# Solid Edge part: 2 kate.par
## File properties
Author: Henri
Template: Normal.par
Last saved by: Henri
Revision: 46
Application: Solid Edge
Accuracy: 0,990
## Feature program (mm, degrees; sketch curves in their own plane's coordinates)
sketch for "unnamed Protrusion 1" plane through (0, 0, 0) normal (0, 0, 1) x-axis (1, 0, 0)
  line (202.5, -60) -> (212.5, -60)
  line (212.5, -60) -> (212.5, -55)
  line (212.5, -55) -> (202.5, -55)
  line (202.5, -55) -> (202.5, -60)
extrude "unnamed Protrusion 1" add finite 10 along -normal
sketch for "ExtrudedProtrusion_2" plane through (0, 0, 0) normal (0, 0, 1) x-axis (1, 0, 0)
  line (261, -467.8017) -> (261, -32.1983)
  line (-262.5, 65.8312) -> (-262.5, -565.8312)
extrude "ExtrudedProtrusion_2" add finite 5 along -normal
fillet "Round_1" radius 1.5
lofted protrusion "unnamed LoftedProtrusion 1"
fillet "Round_15" radius 5
sketch for "ExtrudedCutout_2" plane through (-55, -250, 90) normal (0, 0, 1) x-axis (0, 1, 0)
  line (-225, 137.5) -> (225, 137.5)
  line (225, 137.5) -> (225, -137.5)
  line (-225, -137.5) -> (225, -137.5)
  line (-225, 137.5) -> (-225, -137.5)
extrude "ExtrudedCutout_2" cut finite 5 along -normal
thinwall "Thinwall_6"  Thickness = 5 mm
sketch used by "ExtrudedProtrusion_3" plane through (0, 0, 0) normal (0, 0, 1) x-axis (1, 0, 0)
  line (-207.5, -75) -> (-207.5, -425)
  line (-207.5, -425) -> (242.5, -425)
  line (242.5, -75) -> (242.5, -425)
  line (-207.5, -75) -> (242.5, -75)
  line (-210, -72.5) -> (245, -72.5)
  line (245, -72.5) -> (245, -427.5)
  line (245, -427.5) -> (-210, -427.5)
  line (-210, -72.5) -> (-210, -427.5)
  dimension (linear) = 207.5
  dimension (linear) = 207.5
extrude "ExtrudedProtrusion_3" add finite 42.5 along -normal
sketch for "ExtrudedCutout_4" plane through (0, 0, 0) normal (0, 0, 1) x-axis (1, 0, 0)
extrude "ExtrudedCutout_4" cut finite 40 along -normal
sketch for "ExtrudedCutout_5" plane through (18.5864, -250.0758, 0) normal (0, 0, 1) x-axis (0, 1, 0)
  line (240.0758, -138.9136) -> (175.0758, -138.9136)
  line (175.0758, -78.9136) -> (175.0758, -138.9136)
  line (240.0758, -78.9136) -> (175.0758, -78.9136)
  arc centre (240.0758, -88.9136) radius 10 from (240.0758, -78.9136) to (250.0758, -88.9136) cw
  line (250.0758, -88.9136) -> (250.0758, -128.9136)
  arc centre (240.0758, -128.9136) radius 10 from (250.0758, -128.9136) to (240.0758, -138.9136) cw
extrude "ExtrudedCutout_5" cut finite 40 along -normal
lofted protrusion "unnamed LoftedProtrusion 2"
lofted cutout "unnamed LoftedCutout 1"
fillet "Round_17" radius 1.5
mirror "unnamed Mirror 1" of "ExtrudedCutout_5", "unnamed LoftedProtrusion 2", "unnamed LoftedCutout 1", "Round_17" about plane through (0, -250, 0) normal (0, -1, 0)
extrude "unnamed Cutout 1" cut finite 40
lofted protrusion "unnamed LoftedProtrusion 3"
lofted cutout "unnamed LoftedCutout 2"
fillet "unnamed Round 1"
sketch for "unnamed Cutout 2" #1 plane through (178.0953, -250, 44.6428) normal (0.514496, 0, 0.857493) x-axis (0, 1, 0)
  line (-205, 61.7735) -> (-15, 61.7735)
  arc centre (-15, 51.7735) radius 10 from (-15, 61.7735) to (-5, 51.7735) cw
  line (-5, 51.7735) -> (-5, -51.7701)
  arc centre (-15, -51.7701) radius 10 from (-15, -61.7701) to (-5, -51.7701) ccw
  line (-15, -61.7701) -> (-205, -61.7701)
  arc centre (-205, -51.7701) radius 10 from (-215, -51.7701) to (-205, -61.7701) ccw
  line (-215, -51.7701) -> (-215, 51.7735)
  arc centre (-205, 51.7735) radius 10 from (-215, 51.7735) to (-205, 61.7735) cw
sketch for "unnamed Cutout 2" #2 plane through (178.0953, -250, 44.6428) normal (0.514496, 0, 0.857493) x-axis (0, 1, 0)
  line (15, 61.7735) -> (205.778, 61.7735)
  arc centre (205.778, 52.5515) radius 9.222 from (215, 52.5515) to (205.778, 61.7735) ccw
  line (215, 52.5515) -> (215, -52.5481)
  arc centre (205.778, -52.5481) radius 9.222 from (205.778, -61.7701) to (215, -52.5481) ccw
  line (205.778, -61.7701) -> (15, -61.7701)
  arc centre (15, -51.7701) radius 10 from (5, -51.7701) to (15, -61.7701) ccw
  line (5, -51.7701) -> (5, 51.7735)
  arc centre (15, 51.7735) radius 10 from (5, 51.7735) to (15, 61.7735) cw
extrude "unnamed Cutout 2" cut through along -normal
sketch for "ExtrudedProtrusion_9" #1 plane through (17.5, -250, -40) normal (0, 0, 1) x-axis (0, 1, 0)
  line (-94.7295, 225) -> (-89.7295, 225)
  line (-89.7295, 97.5) -> (-89.7295, 225)
  line (-175, 97.5) -> (-89.7295, 97.5)
  line (-175, 102.5) -> (-175, 97.5)
  line (-175, 102.5) -> (-94.7295, 102.5)
  line (-94.7295, 102.5) -> (-94.7295, 225)
sketch for "ExtrudedProtrusion_9" #2 plane through (17.5, -250, -40) normal (0, 0, 1) x-axis (0, 1, 0)
  line (89.7295, -30) -> (89.7295, 225)
  line (89.7295, 225) -> (94.7295, 225)
  line (94.7295, -25) -> (94.7295, 225)
  line (94.7295, -25) -> (175, -25)
  line (175, -25) -> (175, -30)
  line (175, -30) -> (89.7295, -30)
extrude "ExtrudedProtrusion_9" add finite 40 along +normal
sketch for "unnamed Protrusion 2" plane through (-55, -475, 87.5) normal (0, 1, 0) x-axis (-1, 0, 0)
  line (25, -87.5) -> (25, -2.5)
  line (30, -2.5) -> (25, -2.5)
  line (30, -2.5) -> (30, -87.5)
  line (30, -87.5) -> (25, -87.5)
extrude "unnamed Protrusion 2" add through along -normal
sketch for "unnamed Protrusion 3" plane through (-55, -25, 87.5) normal (0, -1, 0) x-axis (1, 0, 0)
  line (102.5, -2.5) -> (102.5, -87.5)
  line (97.5, -87.5) -> (102.5, -87.5)
  line (97.5, -2.5) -> (97.5, -87.5)
  line (97.5, -2.5) -> (102.5, -2.5)
extrude "unnamed Protrusion 3" add through along -normal
sketch for "ExtrudedProtrusion_12" #1 plane through (18.5864, -250.0758, 0) normal (0, 0, 1) x-axis (0, 1, 0)
  line (89.8053, -28.9136) -> (89.8053, 226.0864)
  line (89.8053, 226.0864) -> (94.8053, 226.0864)
  line (94.8053, -23.9136) -> (94.8053, 226.0864)
  line (94.8053, -23.9136) -> (225.0758, -23.9136)
  line (225.0758, -23.9136) -> (225.0758, -28.9136)
  line (225.0758, -28.9136) -> (89.8053, -28.9136)
sketch for "ExtrudedProtrusion_12" #2 plane through (18.5864, -250.0758, 0) normal (0, 0, 1) x-axis (0, 1, 0)
  line (-224.9242, 98.5864) -> (-89.6537, 98.5864)
  line (-89.6537, 98.5864) -> (-89.6537, 226.0864)
  line (-94.6537, 226.0864) -> (-89.6537, 226.0864)
  line (-94.6537, 103.5864) -> (-94.6537, 226.0864)
  line (-224.9242, 103.5864) -> (-94.6537, 103.5864)
  line (-224.9242, 103.5864) -> (-224.9242, 98.5864)
extrude "ExtrudedProtrusion_12" add finite 85 along +normal
sketch for "unnamed Cutout 3" #1 plane through (0.1912, -510.5703, 43.2891) normal (0, -0.948683, 0.316228) x-axis (1, 0, 0)
  line (-72.6912, 10.6338) -> (17.3088, 10.6338)
  arc centre (17.3088, 15.6338) radius 5 from (17.3088, 10.6338) to (22.3088, 15.6338) ccw
  line (22.3088, 30.6338) -> (22.3088, 15.6338)
  arc centre (17.3088, 30.6338) radius 5 from (22.3088, 30.6338) to (17.3088, 35.6338) ccw
  line (-72.6912, 35.6338) -> (17.3088, 35.6338)
  arc centre (-72.6912, 30.6338) radius 5 from (-77.6912, 30.6338) to (-72.6912, 35.6338) cw
  line (-77.6912, 30.6338) -> (-77.6912, 15.6338)
  arc centre (-72.6912, 15.6338) radius 5 from (-77.6912, 15.6338) to (-72.6912, 10.6338) ccw
sketch for "unnamed Cutout 3" #2 plane through (0.1912, -510.5703, 43.2891) normal (0, -0.948683, 0.316228) x-axis (1, 0, 0)
  line (-182.6912, 10.6338) -> (-92.6912, 10.6338)
  arc centre (-92.6912, 15.6338) radius 5 from (-92.6912, 10.6338) to (-87.6912, 15.6338) ccw
  line (-87.6912, 30.6338) -> (-87.6912, 15.6338)
  arc centre (-92.6912, 30.6338) radius 5 from (-87.6912, 30.6338) to (-92.6912, 35.6338) ccw
  line (-182.6912, 35.6338) -> (-92.6912, 35.6338)
  arc centre (-182.6912, 30.6338) radius 5 from (-187.6912, 30.6338) to (-182.6912, 35.6338) cw
  line (-187.6912, 30.6338) -> (-187.6912, 15.6338)
  arc centre (-182.6912, 15.6338) radius 5 from (-187.6912, 15.6338) to (-182.6912, 10.6338) ccw
extrude "unnamed Cutout 3" cut through along -normal
sketch for "unnamed Cutout 4" #1 plane through (0.1912, 10.5703, 43.2891) normal (0, 0.948683, 0.316228) x-axis (-1, 0, 0)
  line (0, 0) -> (0, 0)
  arc centre (92.6912, 30.6338) radius 5 from (87.6912, 30.6338) to (92.6912, 35.6338) cw
  line (92.6912, 35.6338) -> (182.6912, 35.6338)
  arc centre (182.6912, 30.6338) radius 5 from (187.6912, 30.6338) to (182.6912, 35.6338) ccw
  line (187.6912, 30.6338) -> (187.6912, 15.6338)
  arc centre (182.6912, 15.6338) radius 5 from (182.6912, 10.6338) to (187.6912, 15.6338) ccw
  line (92.6912, 10.6338) -> (182.6912, 10.6338)
  arc centre (92.6912, 15.6338) radius 5 from (87.6912, 15.6338) to (92.6912, 10.6338) ccw
  line (87.6912, 30.6338) -> (87.6912, 15.6338)
sketch for "unnamed Cutout 4" #2 plane through (0.1912, 10.5703, 43.2891) normal (0, 0.948683, 0.316228) x-axis (-1, 0, 0)
  line (-17.3088, 35.6338) -> (72.6912, 35.6338)
  arc centre (72.6912, 30.6338) radius 5 from (77.6912, 30.6338) to (72.6912, 35.6338) ccw
  line (77.6912, 30.6338) -> (77.6912, 15.6338)
  arc centre (72.6912, 15.6338) radius 5 from (72.6912, 10.6338) to (77.6912, 15.6338) ccw
  line (-17.3088, 10.6338) -> (72.6912, 10.6338)
  arc centre (-17.3088, 15.6338) radius 5 from (-22.3088, 15.6338) to (-17.3088, 10.6338) ccw
  line (-22.3088, 30.6338) -> (-22.3088, 15.6338)
  arc centre (-17.3088, 30.6338) radius 5 from (-22.3088, 30.6338) to (-17.3088, 35.6338) cw
extrude "unnamed Cutout 4" cut through along -normal
sketch for "unnamed Cutout 5" #1 plane through (-212.5, -250, 42.4987) normal (-1, 0, 0) x-axis (0, -1, 0)
  line (224.7295, 17.5013) -> (109.7295, 17.5013)
  arc centre (109.7295, 22.5013) radius 5 from (104.7295, 22.5013) to (109.7295, 17.5013) ccw
  line (104.7295, 27.5013) -> (104.7295, 22.5013)
  arc centre (109.7295, 27.5013) radius 5 from (104.7295, 27.5013) to (109.7295, 32.5013) cw
  line (109.7295, 32.5013) -> (224.7295, 32.5013)
  arc centre (224.7295, 27.5013) radius 5 from (224.7295, 32.5013) to (229.7295, 27.5013) cw
  line (229.7295, 27.5013) -> (229.7295, 22.5013)
  arc centre (224.7295, 22.5013) radius 5 from (229.7295, 22.5013) to (224.7295, 17.5013) cw
sketch for "unnamed Cutout 5" #2 plane through (-212.5, -250, 42.4987) normal (-1, 0, 0) x-axis (0, -1, 0)
  line (-109.7295, 17.5013) -> (-224.7295, 17.5013)
  arc centre (-224.7295, 22.5013) radius 5 from (-229.7295, 22.5013) to (-224.7295, 17.5013) ccw
  line (-229.7295, 27.5013) -> (-229.7295, 22.5013)
  arc centre (-224.7295, 27.5013) radius 5 from (-229.7295, 27.5013) to (-224.7295, 32.5013) cw
  line (-224.7295, 32.5013) -> (-109.7295, 32.5013)
  arc centre (-109.7295, 27.5013) radius 5 from (-109.7295, 32.5013) to (-104.7295, 27.5013) cw
  line (-104.7295, 27.5013) -> (-104.7295, 22.5013)
  arc centre (-109.7295, 22.5013) radius 5 from (-109.7295, 17.5013) to (-104.7295, 22.5013) ccw
extrude "unnamed Cutout 5" cut through along -normal
sketch for "unnamed Protrusion 4" plane through (146.5099, -250.0758, 0) normal (0, 0, 1) x-axis (0, 1, 0)
  arc centre (-4.4242, 34.0099) radius 10 from (-4.4242, 24.0099) to (-14.4242, 34.0099) cw
  line (-14.4242, 53.0099) -> (-14.4242, 34.0099)
  arc centre (-4.4242, 53.0099) radius 10 from (-14.4242, 53.0099) to (-4.4242, 63.0099) cw
  line (-4.4242, 63.0099) -> (4.5758, 63.0099)
  arc centre (4.5758, 53.0099) radius 10 from (4.5758, 63.0099) to (14.5758, 53.0099) cw
  line (14.5758, 53.0099) -> (14.5758, 34.0099)
  arc centre (4.5758, 34.0099) radius 10 from (14.5758, 34.0099) to (4.5758, 24.0099) cw
  line (-4.4242, 24.0099) -> (4.5758, 24.0099)
extrude "unnamed Protrusion 4" add through along +normal
sketch for "unnamed Cutout 6" plane through (146.5099, -250.0758, 0) normal (0, 0, 1) x-axis (0, 1, 0)
  arc centre (-4.4242, 34.0099) radius 3 from (-4.4242, 31.0099) to (-7.4242, 34.0099) cw
  line (-7.4242, 53.0099) -> (-7.4242, 34.0099)
  arc centre (-4.4242, 53.0099) radius 3 from (-7.4242, 53.0099) to (-4.4242, 56.0099) cw
  line (-4.4242, 56.0099) -> (4.5758, 56.0099)
  arc centre (4.5758, 53.0099) radius 3 from (4.5758, 56.0099) to (7.5758, 53.0099) cw
  line (7.5758, 53.0099) -> (7.5758, 34.0099)
  arc centre (4.5758, 34.0099) radius 3 from (7.5758, 34.0099) to (4.5758, 31.0099) cw
  line (-4.4242, 31.0099) -> (4.5758, 31.0099)
extrude "unnamed Cutout 6" cut through along +normal
sketch for "unnamed Cutout 7" plane through (146.5099, -250.0758, 0) normal (0, 0, 1) x-axis (0, 1, 0)
extrude "unnamed Cutout 7" cut through along -normal
fillet "Round_20" radius 5
sketch for "ExtrudedCutout_17" plane through (-212.5, -250, 42.4987) normal (-1, 0, 0) x-axis (0, -1, 0)
extrude "ExtrudedCutout_17" cut finite 10 symmetric
sketch for "unnamed Cutout 8" plane through (47.5, -70.2705, 22.5) normal (1, 0, 0) x-axis (0, 1, 0)
  line (-19.7295, 37) -> (-19.7295, -60)
  line (-19.7295, -60) -> (-69.7295, -60)
  line (-69.7295, -60) -> (-69.7295, 37)
  arc centre (-66.7295, 37) radius 3 from (-69.7295, 37) to (-66.7295, 40) cw
  line (-66.7295, 40) -> (-22.7295, 40)
  arc centre (-22.7295, 37) radius 3 from (-22.7295, 40) to (-19.7295, 37) cw
extrude "unnamed Cutout 8" cut through along -normal
sketch for "ExtrudedProtrusion_19" #1 plane through (74.4134, -250.0013, 0) normal (0, 0, 1) x-axis (0, 1, 0)
sketch for "ExtrudedProtrusion_19" #2 plane through (74.4134, -250.0013, 0) normal (0, 0, 1) x-axis (0, 1, 0)
sketch for "ExtrudedProtrusion_19" #3 plane through (74.4134, -250.0013, 0) normal (0, 0, 1) x-axis (0, 1, 0)
  circle centre (312.0066, 264.4134) radius 1.25
sketch for "ExtrudedProtrusion_19" #4 plane through (74.4134, -250.0013, 0) normal (0, 0, 1) x-axis (0, 1, 0)
  circle centre (313.1686, 134.4134) radius 1.25
sketch for "ExtrudedProtrusion_19" #5 plane through (74.4134, -250.0013, 0) normal (0, 0, 1) x-axis (0, 1, 0)
sketch for "ExtrudedProtrusion_19" #6 plane through (74.4134, -250.0013, 0) normal (0, 0, 1) x-axis (0, 1, 0)
sketch for "ExtrudedProtrusion_19" #7 plane through (74.4134, -250.0013, 0) normal (0, 0, 1) x-axis (0, 1, 0)
sketch for "ExtrudedProtrusion_19" #8 plane through (74.4134, -250.0013, 0) normal (0, 0, 1) x-axis (0, 1, 0)
sketch for "ExtrudedProtrusion_19" #9 plane through (74.4134, -250.0013, 0) normal (0, 0, 1) x-axis (0, 1, 0)
  circle centre (285.719, -125.5866) radius 1.25
sketch for "ExtrudedProtrusion_19" #10 plane through (74.4134, -250.0013, 0) normal (0, 0, 1) x-axis (0, 1, 0)
  circle centre (226.2112, -190.5866) radius 1.25
sketch for "ExtrudedProtrusion_19" #11 plane through (74.4134, -250.0013, 0) normal (0, 0, 1) x-axis (0, 1, 0)
  circle centre (250.0012, -306.6723) radius 1.25
extrude "ExtrudedProtrusion_19" add finite 46 along +normal
swept protrusion "unnamed SweptProtrusion 1"
mirror "unnamed Mirror 2" of "unnamed SweptProtrusion 1", "ExtrudedProtrusion_19" about plane through (0, -250, 0) normal (0, -1, 0)
sketch for "unnamed Protrusion 5" #1
  line (94.7295, -25) -> (94.7295, 225)
  line (94.7295, -25) -> (175, -25)
  line (175, -30) -> (89.7295, -30)
  line (89.7295, -30) -> (89.7295, 225)
  line (89.7295, 225) -> (94.7295, 225)
  line (-89.7295, 97.5) -> (-89.7295, 225)
  line (-94.7295, 225) -> (-89.7295, 225)
  line (175, -25) -> (175, -30)
  line (-175, 102.5) -> (-94.7295, 102.5)
  line (-175, 97.5) -> (-89.7295, 97.5)
  line (-175, 102.5) -> (-175, 97.5)
  line (-94.7295, 102.5) -> (-94.7295, 225)
  dimension (linear) = 175
sketch for "unnamed Protrusion 5" #7
  line (94.7295, -25) -> (94.7295, 225)
  line (94.7295, -25) -> (175, -25)
  line (175, -30) -> (89.7295, -30)
  line (89.7295, -30) -> (89.7295, 225)
  line (89.7295, 225) -> (94.7295, 225)
  line (-89.7295, 97.5) -> (-89.7295, 225)
  line (-94.7295, 225) -> (-89.7295, 225)
  line (175, -25) -> (175, -30)
  line (-175, 102.5) -> (-94.7295, 102.5)
  line (-175, 97.5) -> (-89.7295, 97.5)
  line (-175, 102.5) -> (-175, 97.5)
  line (-94.7295, 102.5) -> (-94.7295, 225)
  dimension (linear) = 175
extrude "unnamed Protrusion 5" add finite 46
swept protrusion "unnamed SweptProtrusion 2"
sketch for "ExtrudedProtrusion_21" plane through (-82.9156, -27.2196, 0) normal (0, 0, 1) x-axis (0, 1, 0)
  line (-42.7804, 114.5844) -> (37.2196, 114.5844)
  arc centre (37.2196, 109.5844) radius 5 from (37.2196, 114.5844) to (42.2196, 109.5844) cw
  line (42.2196, 109.5844) -> (42.2196, 9.5844)
  arc centre (37.2196, 9.5844) radius 5 from (42.2196, 9.5844) to (37.2196, 4.5844) cw
  line (-42.7804, 4.5844) -> (37.2196, 4.5844)
  arc centre (-42.7804, 9.5844) radius 5 from (-47.7804, 9.5844) to (-42.7804, 4.5844) ccw
  line (-47.7804, 109.5844) -> (-47.7804, 9.5844)
  arc centre (-42.7804, 109.5844) radius 5 from (-42.7804, 114.5844) to (-47.7804, 109.5844) ccw
extrude "ExtrudedProtrusion_21" add finite 2.5 along +normal
swept protrusion "unnamed SweptProtrusion 3"
sketch for "ExtrudedProtrusion_22" #1 plane through (-142.5, -30, 2.5) normal (0, 0, 1) x-axis (0, 1, 0)
  circle centre (-25, 51.5) radius 1
sketch for "ExtrudedProtrusion_22" #2 plane through (-142.5, -30, 2.5) normal (0, 0, 1) x-axis (0, 1, 0)
  circle centre (-15, 51.5) radius 1
sketch for "ExtrudedProtrusion_22" #3 plane through (-142.5, -30, 2.5) normal (0, 0, 1) x-axis (0, 1, 0)
  circle centre (-5, 51.5) radius 1
sketch for "ExtrudedProtrusion_22" #4 plane through (-142.5, -30, 2.5) normal (0, 0, 1) x-axis (0, 1, 0)
  circle centre (5, 51.5) radius 1
sketch for "ExtrudedProtrusion_22" #5 plane through (-142.5, -30, 2.5) normal (0, 0, 1) x-axis (0, 1, 0)
  circle centre (15, 51.5) radius 1
sketch for "ExtrudedProtrusion_22" #6 plane through (-142.5, -30, 2.5) normal (0, 0, 1) x-axis (0, 1, 0)
  circle centre (25, 51.5) radius 1
extrude "ExtrudedProtrusion_22" add finite 20 along +normal
sketch for "unnamed Protrusion 6" plane through (-142.5, -30, 2.5) normal (0, 0, 1) x-axis (0, 1, 0)
  line (42.5, 47) -> (42.5, -50)
  arc centre (40, -50) radius 2.5 from (42.5, -50) to (40, -52.5) cw
  line (-40, -52.5) -> (40, -52.5)
  arc centre (-40, -50) radius 2.5 from (-42.5, -50) to (-40, -52.5) ccw
  line (-42.5, 47) -> (-42.5, -50)
  arc centre (-40, 47) radius 2.5 from (-42.5, 47) to (-40, 49.5) cw
  line (-40, 49.5) -> (40, 49.5)
  arc centre (40, 47) radius 2.5 from (40, 49.5) to (42.5, 47) cw
extrude "unnamed Protrusion 6" add finite 7.5 along +normal
fillet "unnamed Round 2"
fillet "Round_23" radius 0.95
fillet "Round_24" radius 1.5
sketch for "ExtrudedProtrusion_25" plane through (-82.9156, -27.2196, 0) normal (0, 0, 1) x-axis (0, 1, 0)
  line (-15.2804, -30.4156) -> (19.7196, -30.4156)
  arc centre (19.7196, -32.9156) radius 2.5 from (19.7196, -30.4156) to (22.2196, -32.9156) cw
  line (22.2196, -32.9156) -> (22.2196, -117.9156)
  arc centre (19.7196, -117.9156) radius 2.5 from (19.7196, -120.4156) to (22.2196, -117.9156) ccw
  line (19.7196, -120.4156) -> (-15.2804, -120.4156)
  arc centre (-15.2804, -117.9156) radius 2.5 from (-15.2804, -120.4156) to (-17.7804, -117.9156) cw
  line (-17.7804, -117.9156) -> (-17.7804, -32.9156)
  arc centre (-15.2804, -32.9156) radius 2.5 from (-17.7804, -32.9156) to (-15.2804, -30.4156) cw
extrude "ExtrudedProtrusion_25" add finite 40 along +normal
sketch for "unnamed Cutout 9" plane through (-7.5, -25, 40) normal (0, 0, 1) x-axis (0, 1, 0)
  line (-20, 37.5) -> (7.5, 37.5)
  arc centre (7.5, 35) radius 2.5 from (10, 35) to (7.5, 37.5) ccw
  line (10, 35) -> (10, -35)
  arc centre (7.5, -35) radius 2.5 from (7.5, -37.5) to (10, -35) ccw
  line (-20, -37.5) -> (7.5, -37.5)
  line (-20, 37.5) -> (-20, -37.5)
extrude "unnamed Cutout 9" cut finite 20 along -normal
fillet "unnamed Round 3"
sketch for "RevolvedProtrusion_5" plane through (-67.5, -75.1327, 22.5025) normal (1, 0, 0) x-axis (0, 1, 0)
  line (-19.8673, -42.5025) -> (-9.8673, -42.5025)
  line (-9.8673, -42.5025) -> (-9.8673, -32.5025)
  line (-9.8673, -32.5025) -> (0.1327, -32.5025)
  line (0.1327, -32.5025) -> (0.1327, -62.5025)
  line (0.1327, -62.5025) -> (-29.8673, -62.5025)
  line (-29.8673, -62.5025) -> (-29.8673, -52.5025)
  line (-29.8673, -52.5025) -> (-19.8673, -52.5025)
  line (-19.8673, -52.5025) -> (-19.8673, -42.5025)
revolve "RevolvedProtrusion_5" add finite 90 deg  FiniteAngle2 = 90 deg
fillet "Round_26" radius 1.5
sketch for "ExtrudedProtrusion_26" #1 plane through (-82.5, -155.2705, 22.5) normal (0, 1, 0) x-axis (0, 0, -1)
  line (-32.5, 110) -> (-32.5, 40)
  line (-32.5, 40) -> (52.5, 40)
  line (52.5, 110) -> (52.5, 40)
  line (52.5, 110) -> (-32.5, 110)
sketch for "ExtrudedProtrusion_26" #2 plane through (-82.5, -155.2705, 22.5) normal (0, 1, 0) x-axis (0, 0, -1)
  line (-31, 108.5) -> (-31, 76)
  line (-31, 76) -> (-21, 76)
  line (-21, 108.5) -> (-21, 76)
  line (-21, 108.5) -> (-31, 108.5)
sketch for "ExtrudedProtrusion_26" #3 plane through (-82.5, -155.2705, 22.5) normal (0, 1, 0) x-axis (0, 0, -1)
  line (-20, 108.5) -> (-20, 76)
  line (-20, 76) -> (-10, 76)
  line (-10, 108.5) -> (-10, 76)
  line (-10, 108.5) -> (-20, 108.5)
sketch for "ExtrudedProtrusion_26" #4 plane through (-82.5, -155.2705, 22.5) normal (0, 1, 0) x-axis (0, 0, -1)
  line (-9, 76) -> (-9, 108.5)
  line (41, 108.5) -> (-9, 108.5)
  line (41, 108.5) -> (41, 76)
  line (-9, 76) -> (41, 76)
sketch for "ExtrudedProtrusion_26" #5 plane through (-82.5, -155.2705, 22.5) normal (0, 1, 0) x-axis (0, 0, -1)
  line (42, 108.5) -> (42, 76)
  line (42, 76) -> (51, 76)
  line (51, 76) -> (51, 108.5)
  line (51, 108.5) -> (42, 108.5)
sketch for "ExtrudedProtrusion_26" #6 plane through (-82.5, -155.2705, 22.5) normal (0, 1, 0) x-axis (0, 0, -1)
  line (42, 74) -> (42, 41.5)
  line (42, 41.5) -> (51, 41.5)
  line (51, 41.5) -> (51, 74)
  line (42, 74) -> (51, 74)
sketch for "ExtrudedProtrusion_26" #7 plane through (-82.5, -155.2705, 22.5) normal (0, 1, 0) x-axis (0, 0, -1)
  line (41, 58.5) -> (23, 58.5)
  line (23, 74) -> (23, 58.5)
  line (23, 74) -> (41, 74)
  line (41, 74) -> (41, 58.5)
sketch for "ExtrudedProtrusion_26" #8 plane through (-82.5, -155.2705, 22.5) normal (0, 1, 0) x-axis (0, 0, -1)
  line (23, 57) -> (41, 57)
  line (41, 57) -> (41, 41.5)
  line (23, 41.5) -> (41, 41.5)
  line (23, 57) -> (23, 41.5)
sketch for "ExtrudedProtrusion_26" #9 plane through (-82.5, -155.2705, 22.5) normal (0, 1, 0) x-axis (0, 0, -1)
  line (22, 74) -> (22, 41.5)
  line (7, 41.5) -> (22, 41.5)
  line (7, 74) -> (7, 41.5)
  line (7, 74) -> (22, 74)
sketch for "ExtrudedProtrusion_26" #10 plane through (-82.5, -155.2705, 22.5) normal (0, 1, 0) x-axis (0, 0, -1)
  line (6, 74) -> (6, 41.5)
  line (-9, 41.5) -> (6, 41.5)
  line (-9, 41.5) -> (-9, 74)
  line (-9, 74) -> (6, 74)
sketch for "ExtrudedProtrusion_26" #11 plane through (-82.5, -155.2705, 22.5) normal (0, 1, 0) x-axis (0, 0, -1)
  line (-10, 74) -> (-10, 41.5)
  line (-20, 41.5) -> (-10, 41.5)
  line (-20, 74) -> (-20, 41.5)
  line (-20, 74) -> (-10, 74)
sketch for "ExtrudedProtrusion_26" #12 plane through (-82.5, -155.2705, 22.5) normal (0, 1, 0) x-axis (0, 0, -1)
  line (-21, 74) -> (-21, 41.5)
  line (-31, 41.5) -> (-21, 41.5)
  line (-31, 74) -> (-31, 41.5)
  line (-31, 74) -> (-21, 74)
extrude "ExtrudedProtrusion_26" add finite 25 along +normal
sketch for "unnamed Protrusion 7" #1 plane through (-140.25, -142.7705, -28.5) normal (0, 0, 1) x-axis (-1, 0, 0)
  circle centre (-12.75, -7.5) radius 2.5
sketch for "unnamed Protrusion 7" #2 plane through (-140.25, -142.7705, -28.5) normal (0, 0, 1) x-axis (-1, 0, 0)
  circle centre (-12.75, 7.5) radius 2.5
sketch for "unnamed Protrusion 7" #3 plane through (-140.25, -142.7705, -28.5) normal (0, 0, 1) x-axis (-1, 0, 0)
  circle centre (47.25, 7.5) radius 2.5
sketch for "unnamed Protrusion 7" #4 plane through (-140.25, -142.7705, -28.5) normal (0, 0, 1) x-axis (-1, 0, 0)
  circle centre (47.25, -7.5) radius 2.5
extrude "unnamed Protrusion 7" add finite 11.5 along -normal
sketch for "unnamed Protrusion 8" plane through (-191, -142.7705, 6.5) normal (1, 0, 0) x-axis (0, 1, 0)
  circle centre (0, 21) radius 0.75
extrude "unnamed Protrusion 8" add through along +normal
sketch for "ExtrudedProtrusion_29" plane through (-82.5, -155.2705, 22.5) normal (0, 1, 0) x-axis (-1, 0, 0)
  line (-110, 17.5) -> (-110, 49.1197)
  arc centre (-107.5, 49.1197) radius 2.5 from (-110, 49.1197) to (-107.5, 51.6197) cw
  line (-107.5, 51.6197) -> (-42.5, 51.6197)
  arc centre (-42.5, 49.1197) radius 2.5 from (-40, 49.1197) to (-42.5, 51.6197) ccw
  line (-40, 17.5) -> (-40, 49.1197)
  arc centre (-42.5, 17.5) radius 2.5 from (-42.5, 15) to (-40, 17.5) ccw
  line (-107.5, 15) -> (-42.5, 15)
  arc centre (-107.5, 17.5) radius 2.5 from (-110, 17.5) to (-107.5, 15) ccw
extrude "ExtrudedProtrusion_29" add finite 5 along +normal
sketch for "unnamed Cutout 10" plane through (-7.5, -150.2705, 55.8098) normal (0, 1, 0) x-axis (-1, 0, 0)
  line (-33, -15.8098) -> (-33, 15.8098)
  arc centre (-32.5, 15.8098) radius 0.5 from (-33, 15.8098) to (-32.5, 16.3098) cw
  line (-32.5, 16.3098) -> (32.5, 16.3098)
  arc centre (32.5, 15.8098) radius 0.5 from (32.5, 16.3098) to (33, 15.8098) cw
  line (33, 15.8098) -> (33, -15.8098)
  arc centre (32.5, -15.8098) radius 0.5 from (33, -15.8098) to (32.5, -16.3098) cw
  line (32.5, -16.3098) -> (-32.5, -16.3098)
  arc centre (-32.5, -15.8098) radius 0.5 from (-32.5, -16.3098) to (-33, -15.8098) cw
extrude "unnamed Cutout 10" cut finite 1 along -normal
sketch used by "ExtrudedProtrusion_33" plane through (17.5, -250, -40) normal (0, 0, 1) x-axis (0, 1, 0)
extrude "ExtrudedProtrusion_33" add finite 125 along +normal
sketch used by "unnamed Protrusion 9" plane through (72.5, -425, 42.5) normal (0, -1, 0) x-axis (0, 0, 1)
extrude "unnamed Protrusion 9" add through along +normal
sketch used by "unnamed Protrusion 10" plane through (-5, -472.3648, 0) normal (0, 0, 1) x-axis (0, 1, 0)
extrude "unnamed Protrusion 10" add finite 85 along +normal
sketch for "unnamed Cutout 11" plane through (-5, -425, 22.5) normal (0, 1, 0) x-axis (-1, 0, 0)
  line (-34.6918, 55) -> (-34.6918, -20)
  arc centre (-37.1918, -20) radius 2.5 from (-37.1918, -22.5) to (-34.6918, -20) ccw
  line (-37.1918, -22.5) -> (-67.1918, -22.5)
  arc centre (-67.1918, -20) radius 2.5 from (-67.1918, -22.5) to (-69.6918, -20) cw
  line (-69.6918, -20) -> (-69.6918, 55)
  arc centre (-67.1918, 55) radius 2.5 from (-69.6918, 55) to (-67.1918, 57.5) cw
  line (-67.1918, 57.5) -> (-37.1918, 57.5)
  arc centre (-37.1918, 55) radius 2.5 from (-37.1918, 57.5) to (-34.6918, 55) cw
extrude "unnamed Cutout 11" cut through along -normal
sketch for "unnamed Cutout 12" plane through (-66.25, -339.7295, 22.5) normal (0, 1, 0) x-axis (-1, 0, 0)
  line (-80.9418, 37) -> (-80.9418, -60)
  line (-130.9418, -60) -> (-80.9418, -60)
  line (-130.9418, 37) -> (-130.9418, -60)
  arc centre (-127.9418, 37) radius 3 from (-127.9418, 40) to (-130.9418, 37) ccw
  line (-127.9418, 40) -> (-83.9418, 40)
  arc centre (-83.9418, 37) radius 3 from (-83.9418, 40) to (-80.9418, 37) cw
extrude "unnamed Cutout 12" cut through along -normal
sketch for "ExtrudedProtrusion_36" plane through (70, -384.8648, 22.5) normal (-1, 0, 0) x-axis (0, -1, 0)
  line (21.6352, -42.5) -> (28.6352, -42.5)
  arc centre (28.6352, -41) radius 1.5 from (28.6352, -42.5) to (30.1352, -41) ccw
  line (30.1352, -41) -> (30.1352, -34)
  arc centre (31.6352, -34) radius 1.5 from (30.1352, -34) to (31.6352, -32.5) cw
  line (31.6352, -32.5) -> (40.1352, -32.5)
  line (40.1352, -32.5) -> (40.1352, -62.5)
  line (40.1352, -62.5) -> (10.1352, -62.5)
  line (10.1352, -62.5) -> (10.1352, -54)
  arc centre (11.6352, -54) radius 1.5 from (10.1352, -54) to (11.6352, -52.5) cw
  line (11.6352, -52.5) -> (18.6352, -52.5)
  arc centre (18.6352, -51) radius 1.5 from (18.6352, -52.5) to (20.1352, -51) ccw
  line (20.1352, -51) -> (20.1352, -44)
  arc centre (21.6352, -44) radius 1.5 from (20.1352, -44) to (21.6352, -42.5) cw
extrude "ExtrudedProtrusion_36" add finite 40 along +normal
fillet "Round_30" radius 1.5
mirror "unnamed Mirror 3" of "ExtrudedProtrusion_21", "unnamed SweptProtrusion 3", "ExtrudedProtrusion_22", "unnamed Protrusion 6", "unnamed Round 2", "Round_23", "Round_24" about plane through (0, -250, 0) normal (0, -1, 0)
extrude "unnamed Protrusion 11" add finite 2.5
swept protrusion "unnamed SweptProtrusion 4"
extrude "unnamed Protrusion 12" add finite 20
extrude "unnamed Protrusion 13" add finite 7.5
fillet "unnamed Round 4"
fillet "unnamed Round 5"
fillet "unnamed Round 6"
sketch used by "ExtrudedProtrusion_42" plane through (-5, -472.3648, 0) normal (0, 0, 1) x-axis (0, 1, 0)
extrude "ExtrudedProtrusion_42" add finite 85 along +normal
sketch used by "unnamed Cutout 13" plane through (-7.5, -453.75, 42.5) normal (1, 0, 0) x-axis (0, 1, 0)
extrude "unnamed Cutout 13" cut through along -normal
sketch for "unnamed Cutout 14" plane through (-66.25, -339.7295, 22.5) normal (0, 1, 0) x-axis (-1, 0, 0)
  line (73.75, 37) -> (73.75, -60)
  line (73.75, -60) -> (23.75, -60)
  line (23.75, -60) -> (23.75, 37)
  arc centre (26.75, 37) radius 3 from (23.75, 37) to (26.75, 40) cw
  line (26.75, 40) -> (70.75, 40)
  arc centre (70.75, 37) radius 3 from (70.75, 40) to (73.75, 37) cw
extrude "unnamed Cutout 14" cut through along -normal
sketch for "ExtrudedProtrusion_43" plane through (-85, -432.2295, 22.5) normal (-1, 0, 0) x-axis (0, -1, 0)
  line (-18.7295, -42.5) -> (-25.7295, -42.5)
  arc centre (-25.7295, -44) radius 1.5 from (-27.2295, -44) to (-25.7295, -42.5) cw
  line (-27.2295, -44) -> (-27.2295, -51)
  arc centre (-28.7295, -51) radius 1.5 from (-28.7295, -52.5) to (-27.2295, -51) ccw
  line (-28.7295, -52.5) -> (-35.7295, -52.5)
  arc centre (-35.7295, -54) radius 1.5 from (-37.2295, -54) to (-35.7295, -52.5) cw
  line (-37.2295, -54) -> (-37.2295, -62.5)
  line (-7.2295, -62.5) -> (-37.2295, -62.5)
  line (-7.2295, -32.5) -> (-7.2295, -62.5)
  line (-7.2295, -32.5) -> (-15.7295, -32.5)
  arc centre (-15.7295, -34) radius 1.5 from (-17.2295, -34) to (-15.7295, -32.5) cw
  line (-17.2295, -34) -> (-17.2295, -41)
  arc centre (-18.7295, -41) radius 1.5 from (-18.7295, -42.5) to (-17.2295, -41) ccw
extrude "ExtrudedProtrusion_43" add finite 50 along +normal
fillet "Round_37" radius 1
sketch for "ExtrudedProtrusion_44" #1 plane through (-207.5, -424.8673, 22.5025) normal (1, 0, 0) x-axis (0, 1, 0)
  line (0, 0) -> (0, 0)
  line (15.1377, -57.5025) -> (15.1377, 32.4975)
  line (15.1377, 32.4975) -> (75.1377, 32.4975)
  line (75.1377, 32.4975) -> (75.1377, -57.5025)
  line (75.1377, -57.5025) -> (15.1377, -57.5025)
sketch for "ExtrudedProtrusion_44" #2 plane through (-207.5, -424.8673, 22.5025) normal (1, 0, 0) x-axis (0, 1, 0)
  line (16.6377, 16.5847) -> (43.6377, 16.5847)
  line (43.6377, 30.9975) -> (43.6377, 16.5847)
  line (16.6377, 30.9975) -> (43.6377, 30.9975)
  line (16.6377, 16.5847) -> (16.6377, 30.9975)
sketch for "ExtrudedProtrusion_44" #3 plane through (-207.5, -424.8673, 22.5025) normal (1, 0, 0) x-axis (0, 1, 0)
  line (46.6377, 30.9975) -> (46.6377, 16.5847)
  line (46.6377, 16.5847) -> (73.6377, 16.5847)
  line (73.6377, 30.9975) -> (73.6377, 16.5847)
  line (46.6377, 30.9975) -> (73.6377, 30.9975)
sketch for "ExtrudedProtrusion_44" #4 plane through (-207.5, -424.8673, 22.5025) normal (1, 0, 0) x-axis (0, 1, 0)
  line (46.6377, 15.5847) -> (73.6377, 15.5847)
  line (73.6377, 15.5847) -> (73.6377, 0.5847)
  line (46.6377, 0.5847) -> (73.6377, 0.5847)
  line (46.6377, 15.5847) -> (46.6377, 0.5847)
sketch for "ExtrudedProtrusion_44" #5 plane through (-207.5, -424.8673, 22.5025) normal (1, 0, 0) x-axis (0, 1, 0)
  line (43.6377, 15.5847) -> (43.6377, 0.5847)
  line (16.6377, 0.5847) -> (43.6377, 0.5847)
  line (16.6377, 0.5847) -> (16.6377, 15.5847)
  line (16.6377, 15.5847) -> (43.6377, 15.5847)
sketch for "ExtrudedProtrusion_44" #6 plane through (-207.5, -424.8673, 22.5025) normal (1, 0, 0) x-axis (0, 1, 0)
  line (43.6377, -0.4153) -> (43.6377, -15.4153)
  line (43.6377, -15.4153) -> (16.6377, -15.4153)
  line (16.6377, -15.4153) -> (16.6377, -0.4153)
  line (16.6377, -0.4153) -> (43.6377, -0.4153)
sketch for "ExtrudedProtrusion_44" #7 plane through (-207.5, -424.8673, 22.5025) normal (1, 0, 0) x-axis (0, 1, 0)
  line (46.6377, -0.4153) -> (46.6377, -15.4153)
  line (73.6377, -15.4153) -> (46.6377, -15.4153)
  line (73.6377, -0.4153) -> (73.6377, -15.4153)
  line (46.6377, -0.4153) -> (73.6377, -0.4153)
sketch for "ExtrudedProtrusion_44" #8 plane through (-207.5, -424.8673, 22.5025) normal (1, 0, 0) x-axis (0, 1, 0)
  line (46.6377, -16.4153) -> (46.6377, -36.4153)
  line (46.6377, -36.4153) -> (73.6377, -36.4153)
  line (73.6377, -16.4153) -> (73.6377, -36.4153)
  line (46.6377, -16.4153) -> (73.6377, -16.4153)
sketch for "ExtrudedProtrusion_44" #9 plane through (-207.5, -424.8673, 22.5025) normal (1, 0, 0) x-axis (0, 1, 0)
  line (43.6377, -16.4153) -> (43.6377, -36.4153)
  line (16.6377, -36.4153) -> (43.6377, -36.4153)
  line (16.6377, -36.4153) -> (16.6377, -16.4153)
  line (16.6377, -16.4153) -> (43.6377, -16.4153)
sketch for "ExtrudedProtrusion_44" #10 plane through (-207.5, -424.8673, 22.5025) normal (1, 0, 0) x-axis (0, 1, 0)
  line (43.6377, -37.4153) -> (43.6377, -56.0025)
  line (43.6377, -56.0025) -> (16.6377, -56.0025)
  line (16.6377, -56.0025) -> (16.6377, -37.4153)
  line (43.6377, -37.4153) -> (16.6377, -37.4153)
sketch for "ExtrudedProtrusion_44" #11 plane through (-207.5, -424.8673, 22.5025) normal (1, 0, 0) x-axis (0, 1, 0)
  line (46.6377, -37.4153) -> (46.6377, -56.0025)
  line (73.6377, -56.0025) -> (46.6377, -56.0025)
  line (73.6377, -37.4153) -> (73.6377, -56.0025)
  line (73.6377, -37.4153) -> (46.6377, -37.4153)
extrude "ExtrudedProtrusion_44" add finite 25 along +normal
sketch for "ExtrudedProtrusion_45" #1 plane through (-195, -364.7295, -33.5) normal (0, 0, 1) x-axis (0, 1, 0)
  circle centre (-37.5, 7.5) radius 1.25
sketch for "ExtrudedProtrusion_45" #2 plane through (-195, -364.7295, -33.5) normal (0, 0, 1) x-axis (0, 1, 0)
  circle centre (-37.5, -7.5) radius 1.25
sketch for "ExtrudedProtrusion_45" #3 plane through (-195, -364.7295, -33.5) normal (0, 0, 1) x-axis (0, 1, 0)
  circle centre (7.5, 7.5) radius 1.25
sketch for "ExtrudedProtrusion_45" #4 plane through (-195, -364.7295, -33.5) normal (0, 0, 1) x-axis (0, 1, 0)
  circle centre (7.5, -7.5) radius 1.25
extrude "ExtrudedProtrusion_45" add finite 6.5 along -normal
sketch for "ExtrudedProtrusion_46" plane through (75, -429.7295, 22.5) normal (1, 0, 0) x-axis (0, 1, 0)
  line (82.5, -2.5) -> (12.5, -2.5)
  arc centre (12.5, 0) radius 2.5 from (10, 0) to (12.5, -2.5) ccw
  line (10, 0) -> (10, 40)
  arc centre (12.5, 40) radius 2.5 from (10, 40) to (12.5, 42.5) cw
  line (12.5, 42.5) -> (82.5, 42.5)
  arc centre (82.5, 40) radius 2.5 from (85, 40) to (82.5, 42.5) ccw
  line (85, 40) -> (85, 0)
  arc centre (82.5, 0) radius 2.5 from (82.5, -2.5) to (85, 0) ccw
extrude "ExtrudedProtrusion_46" add finite 3.5 along +normal
sketch for "ExtrudedCutout_30" plane through (78.5, -382.2295, 42.5) normal (1, 0, 0) x-axis (0, 1, 0)
  line (-35, -20) -> (-35, 20)
  line (-35, 20) -> (35, 20)
  line (35, 20) -> (35, -20)
  line (35, -20) -> (-35, -20)
extrude "ExtrudedCutout_30" cut finite 1 along -normal
sketch used by "unnamed Cutout 15" plane through (-207.5, -250, 22.5) normal (1, 0, 0) x-axis (0, 1, 0)
extrude "unnamed Cutout 15" cut through along -normal
sketch for "ExtrudedProtrusion_101" plane through (0, -250, 0) normal (0, -1, 0) x-axis (1, 0, 0)
  line (-187.5, -11) -> (-187.5, -20)
  line (-187.5, -20) -> (-178.5, -20)
  line (-178.5, -20) -> (-177.5, -21)
  line (-177.5, -21) -> (-177.5, -30)
  line (-177.5, -30) -> (-168.5, -30)
  line (-168.5, -30) -> (-167.5, -31)
  line (-167.5, -31) -> (-167.5, -40)
  line (-207.5, -40) -> (-167.5, -40)
  line (-207.5, -40) -> (-207.5, -10)
  line (-207.5, -10) -> (-188.5, -10)
  line (-188.5, -10) -> (-187.5, -11)
extrude "ExtrudedProtrusion_101" add finite 50 symmetric
sketch for "RevolvedProtrusion_6" plane through (-187.5, -275, -25) normal (0, -1, 0) x-axis (1, 0, 0)
  line (-20, -15) -> (-20, 15)
  line (-20, 15) -> (-1, 15)
  line (-1, 15) -> (0, 14)
  line (0, 14) -> (0, 5)
  line (0, 5) -> (9, 5)
  line (9, 5) -> (10, 4)
  line (10, 4) -> (10, -5)
  line (10, -5) -> (19, -5)
  line (19, -5) -> (20, -6)
  line (20, -6) -> (20, -15)
  line (20, -15) -> (-20, -15)
revolve "RevolvedProtrusion_6" add finite 90 deg
fillet "Round_42" radius 0.5
swept protrusion "unnamed SweptProtrusion 5"
sketch for "unnamed Protrusion 14" #1 plane through (74.4134, -250.0013, 0) normal (0, 0, 1) x-axis (0, -1, 0)
sketch for "unnamed Protrusion 14" #2 plane through (74.4134, -250.0013, 0) normal (0, 0, 1) x-axis (0, -1, 0)
  circle centre (-105.0013, -331.9133) radius 1
sketch for "unnamed Protrusion 14" #3 plane through (74.4134, -250.0013, 0) normal (0, 0, 1) x-axis (0, -1, 0)
  circle centre (-35.0013, -331.9133) radius 1
sketch for "unnamed Protrusion 14" #4 plane through (74.4134, -250.0013, 0) normal (0, 0, 1) x-axis (0, -1, 0)
  circle centre (34.9987, -331.9133) radius 1
extrude "unnamed Protrusion 14" add through along +normal
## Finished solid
Body 1: solid body, 802 faces, 1943 edges, 1124 vertices.
  Faces by surface: plane 373, cylinder 289, torus 64, blend 22, sphere 22, spline 17, cone 7, offset 4, swept 4
  Edges by curve: line 1210, circle 545, intersection 124, curve on surface 37, ellipse 23, spline 4
Bounding box of the edges (mm; curved faces can reach further): 679.494 x 643.149 x 132.500, from (-262.5, -571.9112, -42.5) to (416.9937, 71.2375, 90).
Cylindrical faces by radius (mm): R0.5 x13, R0.75 x1, R1 x34, R1.25 x26, R1.5 x92, R2.5 x45, R3 x10, R5 x42, R9.222 x2, R10 x19, R20 x2, R30 x2, R40 x1
Conical faces (half-angle, radius in mm at the cone's reference point): 18.4349 deg R15 x4, 45 deg R19 x1, 45 deg R29 x1, 45 deg R39 x1
Toroidal faces (ring radius, tube radius in mm): R0.05 r0.95 x12, R0.5 r1 x3, R1 r1.5 x8, R2.5 r1 x2, R3 r1.5 x9, R3.5 r1.5 x8, R3.9189 r1.5 x4, R5 r2.5 x4, R8.5 r1.5 x1, R11.5 r1.5 x5, R16.0811 r1.5 x4, R18.5 r1.5 x1, R21.5 r1.5 x1, R28.5 r1.5 x1, R31.5 r1.5 x1
Spherical faces by radius (mm): R1.5 x15, R2.5 x7
Planar faces by outward normal: +x 61, +y 60, +z 79, -x 46, -y 42, -z 45, oblique 40
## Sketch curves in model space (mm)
line (78.5, -417.2295, 62.5) -> (78.5, -347.2295, 62.5)
line (78.5, -347.2295, 62.5) -> (78.5, -347.2295, 22.5)
line (78.5, -347.2295, 22.5) -> (78.5, -417.2295, 22.5)
line (78.5, -417.2295, 22.5) -> (78.5, -417.2295, 62.5)
arc centre (75, -347.2295, 62.5) radius 2.5 from (75, -344.7295, 62.5) through (75, -345.5139, 64.3184) to (75, -347.2295, 65)
line (75, -344.7295, 62.5) -> (75, -344.7295, 22.5)
arc centre (75, -347.2295, 22.5) radius 2.5 from (75, -347.2295, 20) through (75, -345.4111, 20.7844) to (75, -344.7295, 22.5)
line (75, -347.2295, 20) -> (75, -417.2295, 20)
arc centre (75, -417.2295, 22.5) radius 2.5 from (75, -419.7295, 22.5) through (75, -418.9451, 20.6816) to (75, -417.2295, 20)
line (75, -419.7295, 22.5) -> (75, -419.7295, 62.5)
arc centre (75, -417.2295, 62.5) radius 2.5 from (75, -419.7295, 62.5) through (75, -418.9451, 64.3184) to (75, -417.2295, 65)
line (75, -417.2295, 65) -> (75, -347.2295, 65)
line (-257.5, -425, 35) -> (-257.5, -425, 0)
arc centre (-257.5, -415, 35) radius 10 from (-257.5, -415, 45) through (-257.5, -422.2737, 41.8624) to (-257.5, -425, 35)
line (-257.5, -85, 45) -> (-257.5, -415, 45)
arc centre (-257.5, -85, 35) radius 10 from (-257.5, -75, 35) through (-257.5, -78.1376, 42.2737) to (-257.5, -85, 45)
line (-257.5, -75, 35) -> (-257.5, -75, 0)
circle centre (-187.5, -357.2295, -33.5) radius 1.25
circle centre (-202.5, -357.2295, -33.5) radius 1.25
circle centre (-187.5, -402.2295, -33.5) radius 1.25
circle centre (-202.5, -402.2295, -33.5) radius 1.25
line (-202.5, -412.7556, -33.5) -> (-202.5, -347.5911, -33.5)
line (-187.5, -414.0687, -33.5) -> (-187.5, -348.4118, -33.5)
line (-219.4723, -402.2295, -33.5) -> (-176.6312, -402.2295, -33.5)
line (-175.8105, -357.2295, -33.5) -> (-204.8637, -357.2295, -33.5)
line (-207.5, -275, -10) -> (-188.5, -275, -10)
line (-188.5, -275, -10) -> (-187.5, -275, -11)
line (-187.5, -275, -11) -> (-187.5, -275, -20)
line (-187.5, -275, -20) -> (-178.5, -275, -20)
line (-178.5, -275, -20) -> (-177.5, -275, -21)
line (-177.5, -275, -21) -> (-177.5, -275, -30)
line (-177.5, -275, -30) -> (-168.5, -275, -30)
line (-168.5, -275, -30) -> (-167.5, -275, -31)
line (-167.5, -275, -31) -> (-167.5, -275, -40)
line (-167.5, -275, -40) -> (-207.5, -275, -40)
line (-207.5, -275, -40) -> (-207.5, -275, -10)
line (-10, -477.5, 0) -> (-10, -427.5, 0)
line (-10, -427.5, 0) -> (-7.5, -427.5, 0)
line (-7.5, -480, 0) -> (-7.5, -427.5, 0)
line (-80, -480, 0) -> (-7.5, -480, 0)
line (-80, -480, 0) -> (-80, -477.5, 0)
line (-80, -477.5, 0) -> (-10, -477.5, 0)
line (70, -395, -40) -> (70, -395, -31.5)
arc centre (70, -396.5, -31.5) radius 1.5 from (70, -395, -31.5) through (70, -395.4706, -30.4089) to (70, -396.5, -30)
line (70, -396.5, -30) -> (70, -403.5, -30)
arc centre (70, -403.5, -28.5) radius 1.5 from (70, -403.5, -30) through (70, -404.5911, -29.5294) to (70, -405, -28.5)
line (70, -405, -28.5) -> (70, -405, -21.5)
arc centre (70, -406.5, -21.5) radius 1.5 from (70, -405, -21.5) through (70, -405.4706, -20.4089) to (70, -406.5, -20)
line (70, -406.5, -20) -> (70, -413.5, -20)
arc centre (70, -413.5, -18.5) radius 1.5 from (70, -413.5, -20) through (70, -414.5911, -19.5294) to (70, -415, -18.5)
line (70, -415, -18.5) -> (70, -415, -11.5)
arc centre (70, -416.5, -11.5) radius 1.5 from (70, -415, -11.5) through (70, -415.4706, -10.4089) to (70, -416.5, -10)
line (70, -416.5, -10) -> (70, -425, -10)
line (70, -425, -10) -> (70, -425, -40)
line (70, -425, -40) -> (70, -395, -40)
line (-85, -425, -40) -> (-85, -395, -40)
line (-85, -425, -10) -> (-85, -425, -40)
line (-85, -425, -10) -> (-85, -416.5, -10)
arc centre (-85, -416.5, -11.5) radius 1.5 from (-85, -415, -11.5) through (-85, -415.4706, -10.4089) to (-85, -416.5, -10)
line (-85, -415, -11.5) -> (-85, -415, -18.5)
arc centre (-85, -413.5, -18.5) radius 1.5 from (-85, -413.5, -20) through (-85, -414.5911, -19.5294) to (-85, -415, -18.5)
line (-85, -413.5, -20) -> (-85, -406.5, -20)
arc centre (-85, -406.5, -21.5) radius 1.5 from (-85, -405, -21.5) through (-85, -405.4706, -20.4089) to (-85, -406.5, -20)
line (-85, -405, -21.5) -> (-85, -405, -28.5)
arc centre (-85, -403.5, -28.5) radius 1.5 from (-85, -403.5, -30) through (-85, -404.5911, -29.5294) to (-85, -405, -28.5)
line (-85, -403.5, -30) -> (-85, -396.5, -30)
arc centre (-85, -396.5, -31.5) radius 1.5 from (-85, -395, -31.5) through (-85, -395.4706, -30.4089) to (-85, -396.5, -30)
line (-85, -395, -31.5) -> (-85, -395, -40)
line (14.6918, -339.7295, 59.5) -> (14.6918, -339.7295, -37.5)
arc centre (17.6918, -339.7295, 59.5) radius 3 from (17.6918, -339.7295, 62.5) through (15.5097, -339.7295, 61.5587) to (14.6918, -339.7295, 59.5)
line (61.6918, -339.7295, 62.5) -> (17.6918, -339.7295, 62.5)
arc centre (61.6918, -339.7295, 59.5) radius 3 from (61.6918, -339.7295, 62.5) through (63.874, -339.7295, 61.5587) to (64.6918, -339.7295, 59.5)
line (64.6918, -339.7295, 59.5) -> (64.6918, -339.7295, -37.5)
line (64.6918, -339.7295, -37.5) -> (14.6918, -339.7295, -37.5)
line (-207.5, -349.7295, 55) -> (-207.5, -349.7295, -35)
line (-207.5, -349.7295, -35) -> (-207.5, -409.7295, -35)
line (-207.5, -409.7295, -35) -> (-207.5, -409.7295, 55)
line (-207.5, -409.7295, 55) -> (-207.5, -349.7295, 55)
line (-207.5, -408.2295, 6.0872) -> (-207.5, -381.2295, 6.0872)
line (-207.5, -381.2295, 6.0872) -> (-207.5, -381.2295, -13.9128)
line (-207.5, -408.2295, -13.9128) -> (-207.5, -381.2295, -13.9128)
line (-207.5, -408.2295, -13.9128) -> (-207.5, -408.2295, 6.0872)
line (-207.5, -378.2295, -13.9128) -> (-207.5, -351.2295, -13.9128)
line (-207.5, -378.2295, 6.0872) -> (-207.5, -378.2295, -13.9128)
line (-207.5, -378.2295, 6.0872) -> (-207.5, -351.2295, 6.0872)
line (-207.5, -351.2295, 6.0872) -> (-207.5, -351.2295, -13.9128)
line (-207.5, -378.2295, -14.9128) -> (-207.5, -378.2295, -33.5)
line (-207.5, -351.2295, -14.9128) -> (-207.5, -378.2295, -14.9128)
line (-207.5, -351.2295, -14.9128) -> (-207.5, -351.2295, -33.5)
line (-207.5, -351.2295, -33.5) -> (-207.5, -378.2295, -33.5)
line (-207.5, -351.2295, 53.5) -> (-207.5, -351.2295, 39.0872)
line (-207.5, -378.2295, 53.5) -> (-207.5, -351.2295, 53.5)
line (-207.5, -378.2295, 53.5) -> (-207.5, -378.2295, 39.0872)
line (-207.5, -378.2295, 39.0872) -> (-207.5, -351.2295, 39.0872)
line (-207.5, -351.2295, 38.0872) -> (-207.5, -351.2295, 23.0872)
line (-207.5, -378.2295, 23.0872) -> (-207.5, -351.2295, 23.0872)
line (-207.5, -378.2295, 38.0872) -> (-207.5, -378.2295, 23.0872)
line (-207.5, -378.2295, 38.0872) -> (-207.5, -351.2295, 38.0872)
line (-207.5, -351.2295, 22.0872) -> (-207.5, -351.2295, 7.0872)
line (-207.5, -351.2295, 7.0872) -> (-207.5, -378.2295, 7.0872)
line (-207.5, -378.2295, 22.0872) -> (-207.5, -378.2295, 7.0872)
line (-207.5, -378.2295, 22.0872) -> (-207.5, -351.2295, 22.0872)
line (-207.5, -381.2295, 53.5) -> (-207.5, -381.2295, 39.0872)
line (-207.5, -408.2295, 39.0872) -> (-207.5, -381.2295, 39.0872)
line (-207.5, -408.2295, 39.0872) -> (-207.5, -408.2295, 53.5)
line (-207.5, -408.2295, 53.5) -> (-207.5, -381.2295, 53.5)
line (-207.5, -381.2295, 38.0872) -> (-207.5, -381.2295, 23.0872)
line (-207.5, -408.2295, 23.0872) -> (-207.5, -381.2295, 23.0872)
line (-207.5, -408.2295, 23.0872) -> (-207.5, -408.2295, 38.0872)
line (-207.5, -408.2295, 38.0872) -> (-207.5, -381.2295, 38.0872)
line (-207.5, -381.2295, 22.0872) -> (-207.5, -381.2295, 7.0872)
line (-207.5, -381.2295, 7.0872) -> (-207.5, -408.2295, 7.0872)
line (-207.5, -408.2295, 7.0872) -> (-207.5, -408.2295, 22.0872)
line (-207.5, -408.2295, 22.0872) -> (-207.5, -381.2295, 22.0872)
line (-207.5, -408.2295, -33.5) -> (-207.5, -408.2295, -14.9128)
line (-207.5, -381.2295, -33.5) -> (-207.5, -408.2295, -33.5)
line (-207.5, -381.2295, -14.9128) -> (-207.5, -381.2295, -33.5)
line (-207.5, -381.2295, -14.9128) -> (-207.5, -408.2295, -14.9128)
line (-7.5, -445, 82.5) -> (-7.5, -445, 2.5)
line (-7.5, -445, 2.5) -> (-7.5, -475, 2.5)
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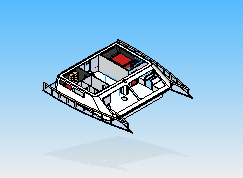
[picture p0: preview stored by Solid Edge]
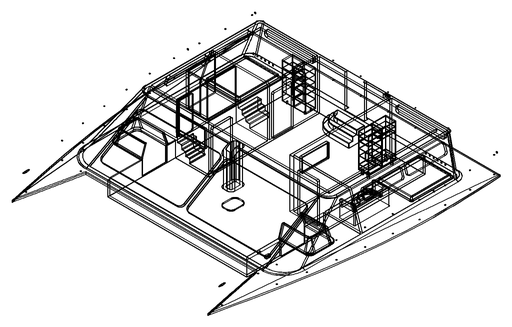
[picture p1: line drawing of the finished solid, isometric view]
